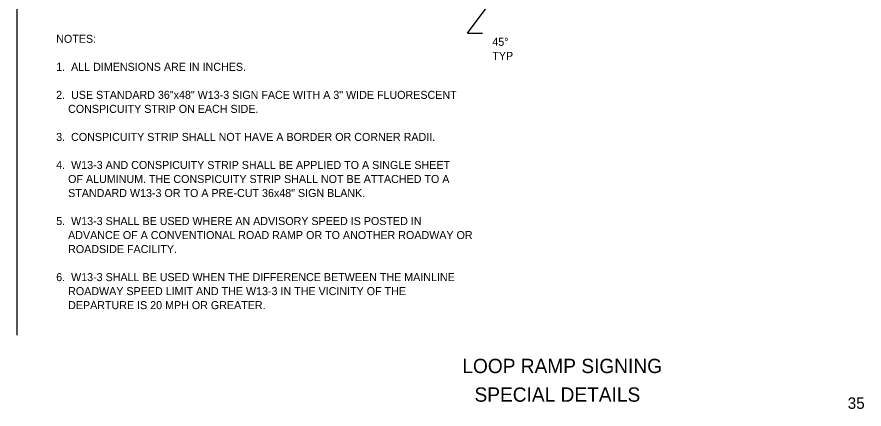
# Model space of a CAD drawing. Extents: x 582908 to 586040, y 1530940 to 1533040.
# Drawn here: x 584558 to 586040, y 1530991 to 1531676 of the extents above; entities that cross this region are included whole.
import ezdxf

# ---------------------------------------------------------------- set-up
doc = ezdxf.new("R2010")
doc.units = 0
for name, color, linetype in [('GSDims', 7, 'Continuous'), ('SheetLinesMisc2_dp', 7, 'Continuous'), ('TextMisc', 7, 'Continuous'), ('TextNotes', 7, 'Continuous'), ('TextShtNo', 7, 'Continuous')]:
    doc.layers.add(name, color=color, linetype=linetype)

msp = doc.modelspace()

# ---------------------------------------------------------------- linework, layer by layer
at = {"layer": 'GSDims'}
for q in [(585387.6, 1531702.7), (585372.4, 1531647.2)]:
    msp.add_line((585346, 1531647.2), q, dxfattribs=at)
at = {"layer": 'SheetLinesMisc2_dp'}
msp.add_line((584558.3, 1533039.8), (584558.3, 1531119.8), dxfattribs=at)

# ---------------------------------------------------------------- texts
at = {"layer": 'GSDims'}
for s, p in [('45°', (585389.6, 1531625.3)), ('TYP', (585389.6, 1531600.8))]:
    msp.add_text(s, height=14, dxfattribs=at).set_placement(p)
at = {"layer": 'TextMisc'}
for s, p in [('   LOOP RAMP SIGNING    ', (585309.3, 1531053.3)), ('    SPECIAL DETAILS     ', (585321.3, 1531003.3))]:
    msp.add_text(s, height=25, rotation=360, dxfattribs=at).set_placement(p)
at = {"layer": 'TextNotes'}
for s, p in [('NOTES:', (584627, 1531630.6)), ('1.  ALL DIMENSIONS ARE IN INCHES.', (584627, 1531581.6)), ('2.  USE STANDARD 36"x48" W13-3 SIGN FACE WITH A 3" WIDE FLUORESCENT', (584627, 1531532.6)), ('    CONSPICUITY STRIP ON EACH SIDE. ', (584627, 1531508.1)), ('3.  CONSPICUITY STRIP SHALL NOT HAVE A BORDER OR CORNER RADII.', (584627, 1531459.1)), ('4.  W13-3 AND CONSPICUITY STRIP SHALL BE APPLIED TO A SINGLE SHEET', (584627, 1531410.1)), ('    OF ALUMINUM. THE CONSPICUITY STRIP SHALL NOT BE ATTACHED TO A', (584627, 1531385.6)), ('    STANDARD W13-3 OR TO A PRE-CUT 36x48" SIGN BLANK.', (584627, 1531361.1)), ('5.  W13-3 SHALL BE USED WHERE AN ADVISORY SPEED IS POSTED IN', (584627, 1531312.1)), ('    ADVANCE OF A CONVENTIONAL ROAD RAMP OR TO ANOTHER ROADWAY OR', (584627, 1531287.6)), ('    ROADSIDE FACILITY.', (584627, 1531263.1)), ('6.  W13-3 SHALL BE USED WHEN THE DIFFERENCE BETWEEN THE MAINLINE', (584627, 1531214.1)), ('    ROADWAY SPEED LIMIT AND THE W13-3 IN THE VICINITY OF THE ', (584627, 1531189.6)), ('    DEPARTURE IS 20 MPH OR GREATER.', (584627, 1531165.1))]:
    msp.add_text(s, height=14, dxfattribs=at).set_placement(p)
at = {"layer": 'TextShtNo'}
msp.add_text('35', height=20, rotation=360, dxfattribs=at).set_placement((586011, 1530990.8))

doc.saveas('drawing.dxf')
